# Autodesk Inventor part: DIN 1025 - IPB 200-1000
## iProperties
Created: 2007-02
Part Number: DIN 1025 - IPB 200-1000
Material: Stahl, weich, unlegiert
Description: Warmgewalzte I-Träger IPB
Document SubType Name: Modeling
Standard: DIN 1025
Designer: thomas
Standards Organization: DIN
Language: de-DE
Size Designation: IPB 200-1000
Categories: <MemberInstance><Categories><Category DisplayName="Profilstähle" InternalName="089c4875-fa83-4c05-b084-43b9cc11f5ed" Mnemonic="GRDR"><CategoryParameter DisplayN
Stock Number: IPB 200
Density: 7.86 g/cm^3
G_L: 650,000 mm
IsCustomPart: 1
Author: thomas
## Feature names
1. Extrusion1
